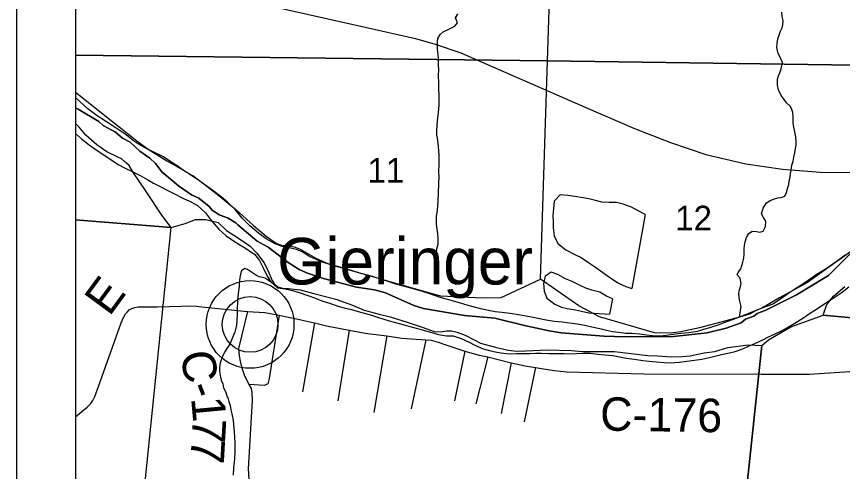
# Model space of a CAD drawing. Extents: x 0 to 34, y 0 to 22.
# Drawn here: x 2 to 3.401, y 16.124 to 16.896 of the extents above; entities that cross this region are included whole.
import ezdxf

# ---------------------------------------------------------------- set-up
doc = ezdxf.new("R2010")
doc.units = 0
for name, color, linetype in [('Default', 7, 'Continuous'), ('GM_X_County_Road', 7, 'Continuous'), ('GM_X_County_Road_Text', 7, 'Continuous'), ('GM_X_Major_River', 7, 'Continuous'), ('GM_X_Minor_Lake', 7, 'Continuous'), ('GM_X_Minor_River', 7, 'Continuous'), ('GM_X_Section', 7, 'Continuous'), ('GM_X_Section_Text', 7, 'Continuous'), ('GM_X_State_Route', 7, 'Continuous'), ('GM_X_Township_Road', 7, 'Continuous'), ('GM_X_Unincorporated', 7, 'Continuous'), ('GM_X_Unincorporated_Location', 7, 'Continuous'), ('GM_X_Unincorporated_Text', 7, 'Continuous'), ('SH_Data', 7, 'Continuous')]:
    doc.layers.add(name, color=color, linetype=linetype)

msp = doc.modelspace()

# ---------------------------------------------------------------- linework, layer by layer
at = {"layer": 'Default'}
for points in [[(2.1, 17.8244), (2.1, 16.8301), (2.9007, 16.8204), (2.9334, 17.8114)], [(2.1, 16.8301), (2.1, 16.7676), (2.1606, 16.7194), (2.174, 16.7088), (2.2041, 16.685), (2.2231, 16.6709), (2.2548, 16.6512), (2.2873, 16.633), (2.3127, 16.6157), (2.3435, 16.5922), (2.3721, 16.5684), (2.4022, 16.5415), (2.4237, 16.5232), (2.4412, 16.511), (2.4498, 16.5078), (2.4642, 16.5067), (2.4729, 16.5046), (2.4811, 16.5014), (2.5091, 16.4851), (2.5335, 16.4747), (2.5486, 16.4705), (2.6829, 16.4321), (2.7194, 16.4221), (2.7909, 16.4188), (2.8224, 16.4192), (2.889, 16.4502), (2.9007, 16.8204)], [(2.1, 16.7143), (2.1, 16.5512), (2.2623, 16.5381), (2.2465, 16.5586), (2.2202, 16.599), (2.1975, 16.6325), (2.1913, 16.6433), (2.1832, 16.6499), (2.1783, 16.6542), (2.1705, 16.6578), (2.1533, 16.6665), (2.1361, 16.6779), (2.1176, 16.6943), (2.1065, 16.7082)], [(2.1, 16.5512), (2.1, 15.5702), (2.1629, 15.5646), (2.2623, 16.5381)]]:
    msp.add_lwpolyline(points, close=True, dxfattribs=at)
at = {"layer": 'GM_X_County_Road'}
for points in [[(2.1, 16.2169), (2.1032, 16.2198), (2.1107, 16.2259), (2.12, 16.2332), (2.1261, 16.2395), (2.1295, 16.2446), (2.133, 16.2515), (2.1389, 16.2681), (2.1775, 16.3763), (2.1817, 16.3852), (2.185, 16.3917), (2.1882, 16.3951), (2.1912, 16.3981), (2.1956, 16.4008), (2.2005, 16.4022), (2.2061, 16.4031), (2.2095, 16.4035), (2.2386, 16.4035), (2.2796, 16.4043), (2.2909, 16.4048), (2.3052, 16.4045), (2.3144, 16.4034), (2.3921, 16.3955)], [(2.3921, 16.3955), (2.3769, 16.3329), (2.3775, 16.3202), (2.3793, 16.3111), (2.3818, 16.3014), (2.386, 16.2882), (2.394, 16.2715), (2.3982, 16.2649), (2.399, 16.2576), (2.3996, 16.2443), (2.3932, 16.1285), (2.3942, 16.111)], [(2.3921, 16.3955), (2.4214, 16.3937), (2.4456, 16.3893), (2.4561, 16.3872), (2.4749, 16.3833), (2.5054, 16.3761), (2.526, 16.3713), (2.5647, 16.364), (2.5913, 16.3589), (2.6281, 16.3544), (2.6538, 16.3502), (2.6947, 16.3474), (2.7035, 16.347), (2.7156, 16.3435), (2.7283, 16.339), (2.7606, 16.328), (2.7848, 16.3216), (2.7998, 16.3187), (2.8391, 16.3083), (2.863, 16.3032), (2.8806, 16.3002), (2.8908, 16.2987), (2.912, 16.2954), (2.9336, 16.2931), (3.0645, 16.29), (3.2641, 16.2893), (3.3454, 16.2894), (3.4564, 16.2968)]]:
    msp.add_lwpolyline(points, dxfattribs=at)
at = {"layer": 'GM_X_Major_River'}
for points in [[(2.4625, 16.5032), (2.4508, 16.5055), (2.4387, 16.51), (2.4238, 16.5188), (2.4105, 16.5284), (2.396, 16.541), (2.3831, 16.5539), (2.3714, 16.568), (2.3578, 16.5809), (2.347, 16.59), (2.3333, 16.6007), (2.3211, 16.609), (2.3088, 16.6185), (2.2992, 16.6253), (2.2868, 16.6325), (2.2727, 16.6424), (2.2619, 16.6496), (2.2493, 16.6576), (2.2328, 16.6657), (2.2223, 16.671), (2.2123, 16.6762), (2.1992, 16.6846), (2.1862, 16.6949), (2.171, 16.7052), (2.1606, 16.712), (2.1449, 16.722), (2.1345, 16.7292), (2.1212, 16.7395), (2.1075, 16.7517), (2.1, 16.7582)], [(2.1, 16.6974), (2.1105, 16.6881), (2.1231, 16.6779), (2.1368, 16.6687), (2.1498, 16.6599), (2.1621, 16.6516), (2.1737, 16.644), (2.1834, 16.6391), (2.1972, 16.6326), (2.2096, 16.6262), (2.223, 16.6189), (2.2327, 16.6133), (2.2447, 16.6068), (2.2555, 16.6012), (2.2667, 16.5955), (2.2824, 16.5878), (2.2936, 16.5825), (2.3063, 16.5757), (2.3208, 16.5631), (2.3306, 16.5495), (2.3431, 16.535), (2.356, 16.5236), (2.3701, 16.5141), (2.3798, 16.5081), (2.3903, 16.502), (2.4044, 16.4921), (2.4124, 16.482), (2.4178, 16.4704), (2.4253, 16.4554), (2.4314, 16.4457), (2.4429, 16.4358)], [(3.4058, 16.4911), (3.3945, 16.4827), (3.3809, 16.4732), (3.3708, 16.4663), (3.3569, 16.4576), (3.3433, 16.4478), (3.3324, 16.4409), (3.3224, 16.4344), (3.3104, 16.4268), (3.2968, 16.4169), (3.2843, 16.4082), (3.2743, 16.4043), (3.2644, 16.4009), (3.254, 16.3966), (3.2436, 16.3912), (3.2267, 16.3857), (3.2017, 16.3766), (3.1898, 16.3724), (3.1756, 16.3679), (3.1657, 16.3648), (3.1553, 16.3617), (3.14, 16.3595), (3.1275, 16.358), (3.1179, 16.3568), (3.1023, 16.3546), (3.0916, 16.3538), (3.0787, 16.3542), (3.0689, 16.3556), (3.0568, 16.3568), (3.0439, 16.3579), (3.0341, 16.3582), (3.0216, 16.3598), (3.011, 16.3612), (3.0012, 16.3634), (2.9895, 16.3661), (2.9763, 16.3688), (2.9665, 16.3713), (2.9555, 16.3736), (2.9427, 16.3751), (2.926, 16.3772), (2.9124, 16.3783), (2.8988, 16.3807), (2.8871, 16.3829), (2.8739, 16.3856), (2.8641, 16.3874), (2.852, 16.3897), (2.8376, 16.392), (2.8236, 16.394), (2.8123, 16.3951), (2.8006, 16.3974), (2.7877, 16.4001), (2.7772, 16.4027), (2.7663, 16.4057), (2.7516, 16.4099), (2.7414, 16.4129), (2.7298, 16.4163), (2.7188, 16.4193), (2.7012, 16.4255), (2.6873, 16.4301), (2.6692, 16.4353), (2.6436, 16.4421), (2.629, 16.4471), (2.6158, 16.451), (2.6041, 16.4548), (2.5932, 16.4574), (2.5808, 16.4608), (2.5702, 16.4642), (2.5529, 16.4693), (2.5424, 16.4722), (2.5285, 16.4765), (2.5187, 16.4794), (2.5086, 16.4839), (2.4973, 16.4888), (2.4847, 16.4964), (2.4749, 16.5005), (2.4625, 16.5032)], [(2.4429, 16.4358), (2.4558, 16.4339), (2.4682, 16.4309), (2.4795, 16.4275), (2.4941, 16.4228), (2.5073, 16.4179), (2.5182, 16.4137), (2.5309, 16.4095), (2.5456, 16.4045), (2.5558, 16.4019), (2.5682, 16.3989), (2.5795, 16.3955), (2.5923, 16.3921), (2.6025, 16.3891), (2.6126, 16.3857), (2.6322, 16.3798), (2.6578, 16.3726), (2.6695, 16.3695), (2.6804, 16.3669), (2.6921, 16.3635), (2.7045, 16.3597), (2.7162, 16.3567), (2.7298, 16.3544), (2.7411, 16.3544), (2.7543, 16.3498), (2.7681, 16.3433), (2.7779, 16.3384), (2.7917, 16.3323), (2.8026, 16.3293), (2.8151, 16.3267), (2.8261, 16.3248), (2.8367, 16.3237), (2.8484, 16.3241), (2.8598, 16.3241), (2.8709, 16.3245), (2.8804, 16.3246), (2.891, 16.3247), (2.9039, 16.3243), (2.9149, 16.3243), (2.9293, 16.3243), (2.9392, 16.3239), (2.9502, 16.3244), (2.9624, 16.3247), (2.9734, 16.3248), (2.9863, 16.3233), (2.998, 16.3221), (3.0116, 16.3206), (3.023, 16.3187), (3.035, 16.3164), (3.0486, 16.3145), (3.0626, 16.3125), (3.0736, 16.311), (3.0861, 16.3099), (3.099, 16.3087), (3.1096, 16.3084), (3.1241, 16.3095), (3.1374, 16.311), (3.1504, 16.3128), (3.1626, 16.3147), (3.1729, 16.3167), (3.1828, 16.3191), (3.1962, 16.3224), (3.2096, 16.3254), (3.2196, 16.3278), (3.2322, 16.3323), (3.2422, 16.3366), (3.253, 16.3412), (3.2665, 16.3476), (3.2762, 16.3523), (3.2862, 16.3569), (3.3004, 16.364), (3.3101, 16.3694), (3.3205, 16.3756), (3.3341, 16.3839), (3.3438, 16.3908), (3.3543, 16.3977), (3.364, 16.4039), (3.3768, 16.4126), (3.3876, 16.4191), (3.3992, 16.4271), (3.4125, 16.4373)]]:
    msp.add_lwpolyline(points, dxfattribs=at)
at = {"layer": 'GM_X_Minor_Lake'}
for p, q in [((3.0665, 16.5602), (3.0438, 16.4343)), ((3.0114, 16.4169), (3.0062, 16.3912))]:
    msp.add_line(p, q, dxfattribs=at)
for points in [[(3.0665, 16.5602), (3.0549, 16.5662), (3.0436, 16.5722), (3.0293, 16.5775), (3.018, 16.5801), (3.0054, 16.5804), (2.9933, 16.5811), (2.9824, 16.5837), (2.971, 16.5863), (2.9612, 16.588), (2.9476, 16.5907), (2.9355, 16.5925), (2.9226, 16.5936), (2.9124, 16.5825), (2.9109, 16.57), (2.9102, 16.5579), (2.9104, 16.548), (2.9108, 16.5373), (2.9124, 16.524), (2.9185, 16.5109), (2.9319, 16.4999), (2.9473, 16.4923), (2.9578, 16.4871), (2.9708, 16.4784), (2.9809, 16.472), (2.9947, 16.4614), (3.0078, 16.4523), (3.0201, 16.444), (3.034, 16.438), (3.0438, 16.4343)], [(3.0114, 16.4169), (3.0013, 16.4214), (2.9897, 16.4285), (2.9761, 16.4315), (2.9659, 16.4348), (2.9561, 16.4396), (2.9426, 16.4461), (2.9317, 16.4509), (2.9186, 16.4581), (2.907, 16.4622), (2.8969, 16.4556), (2.8943, 16.4432), (2.8951, 16.4302), (2.8997, 16.418), (2.9135, 16.4081), (2.9248, 16.4029), (2.9346, 16.4003), (2.9486, 16.3984), (2.9584, 16.3959), (2.9709, 16.3933), (2.9804, 16.3927), (3.0062, 16.3912)]]:
    msp.add_lwpolyline(points, dxfattribs=at)
at = {"layer": 'GM_X_Minor_River'}
for points in [[(3.227, 16.3858), (3.2294, 16.4037), (3.2271, 16.4129), (3.2262, 16.4187), (3.2257, 16.4259), (3.2262, 16.4308), (3.2279, 16.4357), (3.2297, 16.4432), (3.2277, 16.452), (3.2229, 16.4575), (3.225, 16.4628), (3.229, 16.468), (3.2324, 16.4792), (3.2342, 16.486), (3.2344, 16.4925), (3.2347, 16.5016), (3.2353, 16.5076), (3.2366, 16.5137), (3.2388, 16.5212), (3.2428, 16.5275), (3.2483, 16.5319), (3.2555, 16.5313), (3.2611, 16.5303), (3.2669, 16.532), (3.2706, 16.5398), (3.2713, 16.5486), (3.2677, 16.5551), (3.2641, 16.561), (3.2667, 16.5708), (3.2727, 16.5797), (3.2785, 16.5836), (3.2859, 16.5868), (3.2916, 16.5881), (3.2973, 16.5891), (3.3035, 16.5911), (3.3063, 16.5971), (3.3085, 16.6058), (3.3102, 16.6107), (3.3112, 16.6171), (3.3125, 16.6231), (3.3131, 16.6296), (3.3145, 16.6345), (3.3155, 16.6435), (3.3177, 16.6503), (3.3187, 16.6575), (3.3208, 16.6646), (3.3218, 16.6722), (3.3228, 16.6775), (3.323, 16.6835), (3.3221, 16.6919), (3.3205, 16.7), (3.3189, 16.7084), (3.3176, 16.7157), (3.318, 16.7263), (3.3175, 16.7328), (3.3157, 16.7381), (3.3133, 16.7432), (3.3063, 16.7495), (3.3023, 16.7553), (3.2976, 16.7619), (3.293, 16.7716), (3.2913, 16.7793), (3.2913, 16.7895), (3.2927, 16.7952), (3.2951, 16.8004), (3.2972, 16.8072), (3.2995, 16.8177), (3.2974, 16.8231), (3.2953, 16.8281), (3.2924, 16.8332), (3.2898, 16.8435), (3.2904, 16.85), (3.2918, 16.8579), (3.2939, 16.8639), (3.2956, 16.8699), (3.2989, 16.8766), (3.3002, 16.8815), (3.3008, 16.8891), (3.2992, 16.8956), (3.2983, 16.9033)], [(2.7104, 16.4833), (2.7125, 16.4953), (2.7131, 16.5017), (2.7152, 16.5096), (2.7155, 16.5191), (2.7147, 16.5283), (2.7138, 16.5344), (2.7126, 16.5443), (2.7124, 16.5504), (2.7127, 16.5568), (2.7142, 16.5674), (2.7148, 16.5754), (2.7155, 16.5826), (2.716, 16.5974), (2.7169, 16.6255), (2.7167, 16.6308), (2.7169, 16.6464), (2.7171, 16.6521), (2.717, 16.66), (2.7165, 16.6688), (2.716, 16.6753), (2.7154, 16.6806), (2.7142, 16.6902), (2.7133, 16.6951), (2.7131, 16.702), (2.7138, 16.7114), (2.715, 16.7247), (2.7161, 16.733), (2.7169, 16.7452), (2.7174, 16.7596), (2.7172, 16.7649), (2.7166, 16.7699), (2.7165, 16.7786), (2.7163, 16.7835), (2.716, 16.7957), (2.7163, 16.806), (2.7162, 16.8132), (2.716, 16.8185), (2.7158, 16.8242), (2.7153, 16.8315), (2.7145, 16.8402), (2.7143, 16.8459), (2.7141, 16.8532), (2.7147, 16.8588), (2.7191, 16.8651), (2.7242, 16.8699), (2.7312, 16.8731), (2.7369, 16.8759), (2.7435, 16.8795), (2.7481, 16.8851), (2.7451, 16.8935)], [(2.7483, 16.8997), (2.7451, 16.8935), (2.7488, 16.9006)], [(2.4332, 16.4442), (2.422, 16.4522), (2.4171, 16.4531), (2.4115, 16.4544), (2.407, 16.4565), (2.4022, 16.4597), (2.397, 16.4633), (2.3918, 16.4665), (2.3873, 16.4682), (2.3818, 16.4646), (2.3801, 16.4586), (2.3788, 16.4533), (2.3777, 16.4431), (2.3775, 16.4378), (2.3769, 16.4302), (2.3759, 16.4253), (2.3758, 16.4203), (2.3752, 16.4143), (2.375, 16.4086), (2.3744, 16.404), (2.3743, 16.3987), (2.3744, 16.3911), (2.374, 16.3805), (2.3734, 16.3722), (2.372, 16.3673), (2.3703, 16.3605), (2.3682, 16.3553), (2.3641, 16.3455), (2.362, 16.3403), (2.3568, 16.3329), (2.3532, 16.3273), (2.3504, 16.3217), (2.3483, 16.3164), (2.3466, 16.3119), (2.3449, 16.3055), (2.3443, 16.2991), (2.3445, 16.2942), (2.346, 16.2842), (2.3474, 16.2789), (2.3498, 16.2727), (2.3511, 16.2662), (2.3547, 16.2596), (2.3571, 16.2527), (2.3592, 16.2473), (2.3602, 16.2427), (2.3626, 16.2362), (2.3639, 16.2289), (2.3652, 16.222), (2.3665, 16.2163), (2.3674, 16.2106), (2.3689, 16.1976), (2.3694, 16.1919), (2.3699, 16.1824), (2.3703, 16.1725), (2.3705, 16.1671), (2.3705, 16.1576), (2.3701, 16.1455), (2.3692, 16.1406), (2.3681, 16.1308), (2.3677, 16.1179)]]:
    msp.add_lwpolyline(points, dxfattribs=at)
at = {"layer": 'GM_X_Section'}
for points in [[(3.923, 17.7965), (3.9054, 16.8066), (2.9007, 16.8204), (2.9334, 17.8114)], [(3.2644, 16.338), (3.276, 16.3476), (3.3136, 16.3694), (3.3687, 16.3893), (4.2789, 16.3058), (4.1746, 15.3336), (3.1681, 15.4277)]]:
    msp.add_lwpolyline(points, close=True, dxfattribs=at)
for points in [[(3.4415, 16.5156), (3.3921, 16.48), (3.342, 16.4445), (3.2944, 16.4184), (3.2644, 16.4009), (3.2269, 16.3859), (3.1587, 16.3679), (3.1274, 16.361), (3.11, 16.3588), (3.0823, 16.3595), (2.989, 16.3864), (2.9542, 16.405), (2.889, 16.4502), (2.9007, 16.8204), (3.9054, 16.8066)], [(2.1629, 15.5646), (2.2623, 16.5381), (2.2863, 16.5447), (2.3039, 16.5515), (2.3213, 16.5514), (2.3424, 16.5464), (2.3565, 16.5328), (2.3688, 16.5249), (2.3852, 16.5143), (2.3964, 16.5061), (2.4078, 16.4944), (2.4203, 16.4782), (2.4264, 16.4648), (2.4336, 16.448), (2.4369, 16.4426), (2.4436, 16.4371), (2.4511, 16.435), (2.4613, 16.4344), (2.4711, 16.4334), (2.4813, 16.432), (2.5047, 16.4261), (2.5416, 16.4165), (2.5701, 16.4064), (2.5896, 16.3979), (2.6152, 16.3909), (2.634, 16.3863), (2.663, 16.3776), (2.6882, 16.369), (2.7088, 16.3617), (2.719, 16.3607), (2.7304, 16.3627), (2.738, 16.3625), (2.7474, 16.3604), (2.761, 16.3555), (2.7767, 16.3476), (2.7871, 16.342), (2.8165, 16.3337), (2.8346, 16.3299), (2.8486, 16.3284), (2.8634, 16.3288), (2.8884, 16.3301), (2.9005, 16.3305), (2.9414, 16.3292), (2.9592, 16.3276), (2.9838, 16.3274), (3.0149, 16.3278), (3.0712, 16.3211), (3.0878, 16.3203), (3.1116, 16.3186), (3.1295, 16.3193), (3.1431, 16.3205), (3.1667, 16.3256), (3.1846, 16.3278), (3.2067, 16.3345), (3.2417, 16.3389), (3.2644, 16.338), (3.1681, 15.4277)], [(4.2789, 16.3058), (3.3687, 16.3893), (3.3752, 16.4073), (3.3861, 16.4214), (3.4055, 16.4376)]]:
    msp.add_lwpolyline(points, dxfattribs=at)
at = {"layer": 'GM_X_State_Route'}
for points in [[(2.1, 19.8108), (2.1, 16.7408), (2.1045, 16.7386), (2.1399, 16.7179), (2.1472, 16.7109), (2.1677, 16.6995), (2.1799, 16.6896), (2.193, 16.6827), (2.2095, 16.6673), (2.2262, 16.6557), (2.2361, 16.6466), (2.2467, 16.6322), (2.2751, 16.6084), (2.2969, 16.5936), (2.3093, 16.5875), (2.3267, 16.5736), (2.3321, 16.5673), (2.3436, 16.5597), (2.3582, 16.5542), (2.3724, 16.5461), (2.3753, 16.5422), (2.4081, 16.5149), (2.4268, 16.5047), (2.4612, 16.4785), (2.4794, 16.4669), (2.4939, 16.4603), (2.5206, 16.4514), (2.577, 16.4365), (2.6072, 16.432), (2.6261, 16.4272), (2.6743, 16.4054), (2.6908, 16.4003), (2.7603, 16.3884), (2.8117, 16.3839), (2.8622, 16.3719), (2.9036, 16.3625), (2.9244, 16.3595), (2.9967, 16.3536), (3.0327, 16.3524), (3.1148, 16.3533), (3.1719, 16.359), (3.2041, 16.367), (3.2294, 16.376), (3.2369, 16.3825), (3.2511, 16.3874), (3.2565, 16.3921), (3.2712, 16.3977), (3.3237, 16.424), (3.3719, 16.4533), (3.3778, 16.4566), (3.4267, 16.5055)], [(2.1, 16.9573), (2.1106, 16.9597), (2.1292, 16.9615), (2.1542, 16.9641), (2.1913, 16.9635), (2.2189, 16.9607), (2.2409, 16.957), (2.3294, 16.9372), (2.5918, 16.8775), (2.6768, 16.8583), (2.7102, 16.849), (2.7539, 16.8341), (2.9659, 16.7415), (3.0483, 16.7056), (3.1094, 16.6824), (3.1696, 16.662), (3.2373, 16.6461), (3.2999, 16.6371), (3.3641, 16.6318), (3.4249, 16.631)], [(3.4267, 16.5055), (3.3778, 16.4566), (3.3719, 16.4533), (3.3237, 16.424), (3.2712, 16.3977), (3.2565, 16.3921), (3.2511, 16.3874), (3.2369, 16.3825), (3.2294, 16.376), (3.2041, 16.367), (3.1719, 16.359), (3.1148, 16.3533), (3.0327, 16.3524), (2.9967, 16.3536), (2.9244, 16.3595), (2.9036, 16.3625), (2.8622, 16.3719), (2.8117, 16.3839), (2.7603, 16.3884), (2.6908, 16.4003), (2.6743, 16.4054), (2.6261, 16.4272), (2.6072, 16.432), (2.577, 16.4365), (2.5206, 16.4514), (2.4939, 16.4603), (2.4794, 16.4669), (2.4612, 16.4785), (2.4268, 16.5047), (2.4081, 16.5149), (2.3753, 16.5422), (2.3724, 16.5461), (2.3582, 16.5542), (2.3436, 16.5597), (2.3321, 16.5673), (2.3267, 16.5736), (2.3093, 16.5875), (2.2969, 16.5936), (2.2751, 16.6084), (2.2467, 16.6322), (2.2361, 16.6466), (2.2262, 16.6557), (2.2095, 16.6673), (2.193, 16.6827), (2.1799, 16.6896), (2.1677, 16.6995), (2.1472, 16.7109), (2.1399, 16.7179), (2.1045, 16.7386), (2.1, 16.7408), (2.1, 14.1)]]:
    msp.add_lwpolyline(points, dxfattribs=at)
at = {"layer": 'GM_X_Township_Road'}
for p, q in [((2.5054, 16.3761), (2.4855, 16.2591)), ((2.5647, 16.364), (2.5451, 16.2441)), ((2.6281, 16.3544), (2.6061, 16.2242)), ((2.6947, 16.3474), (2.6696, 16.2302)), ((2.7606, 16.328), (2.7433, 16.2442)), ((2.7998, 16.3187), (2.7796, 16.239)), ((2.8391, 16.3083), (2.8226, 16.2222)), ((2.8806, 16.3002), (2.8611, 16.2084))]:
    msp.add_line(p, q, dxfattribs=at)
msp.add_lwpolyline([(2.4456, 16.3893), (2.4289, 16.2821), (2.4262, 16.2725), (2.4205, 16.2701), (2.394, 16.2715)], dxfattribs=at)
at = {"layer": 'GM_X_Unincorporated'}
for radius in [0.0744, 0.0472]:
    msp.add_circle((2.3964, 16.3735), radius, dxfattribs=at)
at = {"layer": 'GM_X_Unincorporated_Location'}
msp.add_line((2.3964, 16.3735), (2.3964, 16.3735), dxfattribs=at)
at = {"layer": 'SH_Data'}
for p, q in [((2, 21), (2, 14)), ((2.1, 20.9), (2.1, 14.1))]:
    msp.add_line(p, q, dxfattribs=at)

# ---------------------------------------------------------------- texts
at = {"layer": 'GM_X_County_Road_Text'}
for s, height, rotation, p in [('E', 0.0568, 53.7378, (2.1576, 16.3858)), ('C', 0.0568, 278.9514, (2.2781, 16.3251)), ('-', 0.0568, 290.8662, (2.2887, 16.2666)), ('1', 0.0568, 275.2909, (2.2961, 16.2487)), ('C-176', 0.05682, 359.1673, (2.99, 16.1935)), ('7', 0.0568, 266.7139, (2.2993, 16.2161)), ('7', 0.0568, 266.8189, (2.2973, 16.1811))]:
    msp.add_text(s, height=height, rotation=rotation, dxfattribs=at).set_placement(p)
at = {"layer": 'GM_X_Section_Text'}
for s, p in [('11', (2.5956, 16.6139)), ('12', (3.1177, 16.533))]:
    msp.add_text(s, height=0.04186, rotation=0, dxfattribs=at).set_placement(p)
at = {"layer": 'GM_X_Unincorporated_Text'}
msp.add_text('Gieringer', height=0.07898, rotation=0, dxfattribs=at).set_placement((2.4423, 16.4413))

doc.saveas('drawing.dxf')
